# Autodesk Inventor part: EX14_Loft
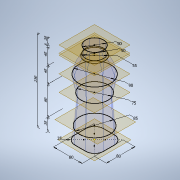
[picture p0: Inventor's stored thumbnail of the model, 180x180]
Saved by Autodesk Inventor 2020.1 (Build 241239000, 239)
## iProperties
Created: 2019-10
Part Number: EX14_Loft
Material: Glass
Document SubType Name: Modeling
Designer: Synergysoft Dell02
Density: 2.18 g/cm^3
Appearance: Clear - Blue
Author: Synergysoft Dell02
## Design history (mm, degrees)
node "Annotations"
  node "Linear Dimension 1" dims "d0" = 80, "d1" = 80, "d2" = 25, "d103" = 35 (derived)
  node "Linear Dimension 2" dims "d0" = 80, "d1" = 80, "d2" = 25, "d106" = 80 (derived)
  node "Linear Dimension 3" dims "d0" = 80, "d1" = 80, "d2" = 25, "d109" = 45 (derived)
  node "Linear Dimension 4" dims "d0" = 80, "d1" = 80, "d2" = 25, "d112" = 45 (derived)
  node "Linear Dimension 5" dims "d0" = 80, "d1" = 80, "d2" = 25, "d115" = 5 (derived)
  node "Linear Dimension 6" dims "d0" = 80, "d1" = 80, "d2" = 25, "d118" = 20 (derived)
  node "Linear Dimension 7" dims "d0" = 80, "d1" = 80, "d2" = 25, "d121" = 230 (derived)
sketch "Sketch1"
  geometry: L1 (15, 40)-(-15, 40); L2 (-40, 15)-(-40, -15); L3 (-15, -40)-(15, -40); L4 (40, -15)-(40, 15); L5 (40, 40)-(-40, -40); L6 (-40, 40)-(40, -40); A1 r 25 centre (15, 15) between (40, 15) and (15, 40); A2 r 25 centre (15, -15) between (15, -40) and (40, -15); A3 r 25 centre (-15, -15) between (-40, -15) and (-15, -40); A4 r 25 centre (-15, 15) between (-15, 40) and (-40, 15); 1 further point
  constraints: 12 end point, 8 point on circle, 8 point on line, 8 tangent, 4 centre point, 3 equal radius, 2 midpoint, 2 parallel, 1 horizontal, 1 perpendicular
  dimensions: "d0" = 80 distance of L6.end L5.end; "d1" = 80 distance of L5.end L6.start; "d2" = 25 radius of A1
workplane "Work Plane1"
sketch "Sketch2"
  geometry: C1 r 42.5 at (0, 0); 1 further point
  constraints: 1 centre point, 1 coincident
  dimensions: "d4" = 85 diameter of C1
workplane "Work Plane2"
sketch "Sketch3"
  geometry: C1 r 37.5 at (0, 0); 1 further point
  constraints: 1 centre point, 1 coincident
  dimensions: "d6" = 75 diameter of C1
workplane "Work Plane3"
sketch "Sketch4"
  geometry: C1 r 45 at (0, 0); 1 further point
  constraints: 1 centre point, 1 coincident
  dimensions: "d8" = 90 diameter of C1
workplane "Work Plane4"
sketch "Sketch5"
  geometry: C1 r 27.5 at (0, 0); 1 further point
  constraints: 1 centre point, 1 coincident
  dimensions: "d10" = 55 diameter of C1
workplane "Work Plane5"
sketch "Sketch9"
  geometry: C1 r 25 at (0, 0); 1 further point
  constraints: 1 centre point, 1 coincident
  dimensions: "d31" = 50 diameter of C1
workplane "Work Plane6"
sketch "Sketch10"
  geometry: C1 r 25 at (0, 0); 1 further point
  constraints: 1 centre point, 1 coincident
  dimensions: "d33" = 50 diameter of C1
node "3D Sketch1" dims "d48" = 250
sketch "Sketch7"
  geometry: L1 (0, 0)-(22.159, 139.709); L2 (22.159, 139.709)-(-29.767, 228.961)
  constraints: 3 other
loft "Loft4" dims "d53" = 0, "d54" = 90 deg, "d55" = 0, "d56" = 90 deg, "d57" = 0, "d58" = 90 deg, "d59" = 0, "d60" = 90 deg, "d61" = 0, "d62" = 90 deg, "d63" = 0, "d64" = 90 deg, "d65" = 0, "d66" = 90 deg
loft "Loft3" dims "d34" = 0, "d35" = 90 deg, "d36" = 0, "d37" = 90 deg, "d38" = 0, "d39" = 90 deg, "d40" = 0, "d41" = 90 deg, "d42" = 0, "d43" = 90 deg, "d44" = 0, "d45" = 90 deg, "d46" = 0, "d47" = 90 deg, "d51" = 0, "d52" = 90 deg
loft "Loft5" dims "d67" = 0, "d68" = 90 deg, "d69" = 0, "d70" = 90 deg, "d71" = 0, "d72" = 90 deg
loft "Loft6" dims "d73" = 0, "d74" = 90 deg, "d75" = 0, "d76" = 90 deg, "d77" = 0, "d78" = 90 deg, "d79" = 0, "d80" = 90 deg, "d81" = 0, "d82" = 0, "d83" = 586.34954, "d84" = 10, "d85" = 115, "d86" = 5.60976, "d87" = 441.78647, "d88" = 10, "d89" = 205, "d90" = 10, "d91" = 237.58294, "d92" = 10, "d93" = 123, "d94" = 6, "d95" = 520, "d96" = 11.21129
workplane "Work Plane7"
body "Solid1"
body "Solid2"
body "Solid3"
body "Solid4"
body "Solid5"
other parameters: "d3" = 35, "d7" = 45, "d9" = 45, "d11" = 5, "d101" = 42.39227 (derived), "d102" = 51.06059 (derived), "d104" = 69.46425 (derived), "d105" = 4.41172 (derived), "d107" = 49.69544 (derived), "d108" = 28.12557 (derived), "d110" = 49.69544 (derived), "d111" = 49.69544 (derived), "d113" = 36.30996 (derived), "d114" = 49.69544 (derived), "d116" = 38.75978 (derived), "d117" = 49.69544 (derived), "d119" = 43.02019 (derived), "d120" = 49.69544 (derived)
